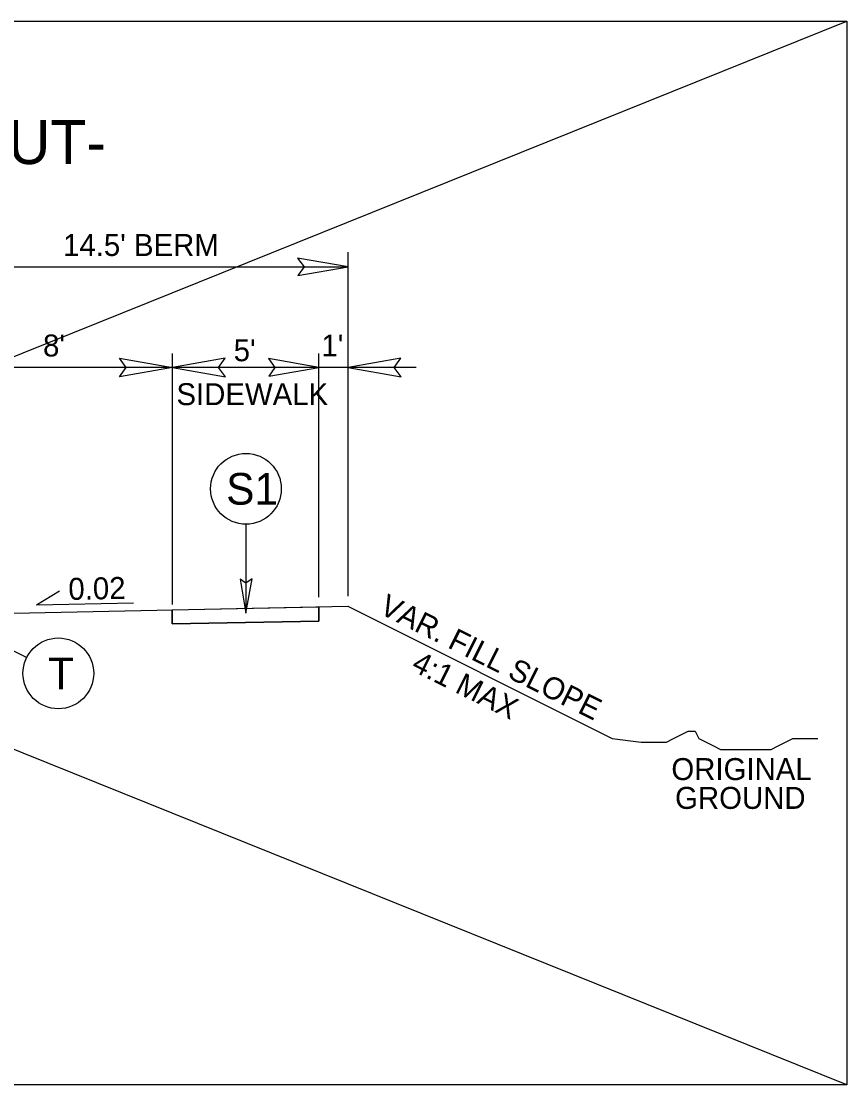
# Model space of a CAD drawing. Extents: x 1487909 to 1489267, y 497866 to 499814.
# Drawn here: x 1489239.04 to 1489267.23, y 498144.27 to 498180.57 of the extents above; entities that cross this region are included whole.
import ezdxf

# ---------------------------------------------------------------- set-up
doc = ezdxf.new("R2010")
doc.units = 0
for name, color, linetype in [('Prop Conc 4in Sidewalk', 7, 'Continuous'), ('Prop Dimension', 7, 'Continuous'), ('Prop Dimension Text', 7, 'Continuous'), ('Prop Shade Light', 7, 'Continuous'), ('Prop Terminator CELL', 7, 'Continuous'), ('Scratch_Level_3', 7, 'Continuous'), ('Typical Hinge Slope Arterial CELL', 7, 'Continuous'), ('Typical Hinge Slope Interstate CELL', 7, 'Continuous'), ('Typical ID Circle CELL', 7, 'Continuous'), ('Typical Pavement Slope CELL', 7, 'Continuous'), ('Typical Pavement Slope Information CELL', 7, 'Continuous'), ('Typical Terminator CELL', 7, 'Continuous'), ('Typical Text ID Circle CELL', 7, 'Continuous')]:
    doc.layers.add(name, color=color, linetype=linetype)

msp = doc.modelspace()

# ---------------------------------------------------------------- linework, layer by layer
at = {"layer": 'Prop Conc 4in Sidewalk'}
for p, q in [((1489244.198, 498160.48), (1489249.198, 498160.58)), ((1489249.198, 498160.099), (1489249.198, 498160.58)), ((1489244.198, 498160.48), (1489244.198, 498159.999)), ((1489244.198, 498159.999), (1489249.198, 498160.099))]:
    msp.add_line(p, q, dxfattribs=at)
at = {"layer": 'Prop Dimension'}
for p, q in [((1489250.199, 498160.943), (1489250.199, 498172.686)), ((1489235.699, 498172.186), (1489250.199, 498172.186)), ((1489244.199, 498160.664), (1489244.199, 498169.227)), ((1489249.199, 498160.912), (1489249.199, 498169.227)), ((1489244.199, 498168.756), (1489236.199, 498168.756)), ((1489249.199, 498168.756), (1489244.199, 498168.756)), ((1489250.199, 498168.756), (1489249.199, 498168.756)), ((1489252.529, 498168.756), (1489250.199, 498168.756))]:
    msp.add_line(p, q, dxfattribs=at)
at = {"layer": 'Prop Shade Light'}
for p, q in [((1489244.198, 498160.48), (1489249.198, 498160.58)), ((1489249.198, 498160.58), (1489249.198, 498160.099)), ((1489244.198, 498159.999), (1489244.198, 498160.48)), ((1489249.198, 498160.099), (1489244.198, 498159.999))]:
    msp.add_line(p, q, dxfattribs=at)
at = {"layer": 'Prop Terminator CELL'}
for points in [[(1489248.489, 498171.891), (1489250.199, 498172.186), (1489248.479, 498172.49), (1489248.698, 498172.186)], [(1489242.399, 498169.066), (1489244.199, 498168.756), (1489242.389, 498168.436), (1489242.619, 498168.756)], [(1489245.999, 498169.066), (1489244.199, 498168.756), (1489246.009, 498168.436), (1489245.779, 498168.756)], [(1489247.489, 498168.461), (1489249.199, 498168.756), (1489247.479, 498169.06), (1489247.698, 498168.756)], [(1489251.999, 498169.066), (1489250.199, 498168.756), (1489252.009, 498168.436), (1489251.779, 498168.756)]]:
    msp.add_lwpolyline(points, close=True, dxfattribs=at)
at = {"layer": 'Scratch_Level_3'}
for p, q in [((1489176.952, 498144.269), (1489267.234, 498180.571)), ((1489267.234, 498144.269), (1489176.952, 498180.571))]:
    msp.add_line(p, q, dxfattribs=at)
msp.add_lwpolyline([(1489176.952, 498180.571), (1489267.234, 498180.571), (1489267.234, 498144.269), (1489176.952, 498144.269)], close=True, dxfattribs=at)
at = {"layer": 'Typical Hinge Slope Arterial CELL'}
msp.add_line((1489250.198, 498160.6), (1489259.227, 498156.086), dxfattribs=at)
msp.add_lwpolyline([(1489259.227, 498156.086), (1489260.213, 498155.963), (1489260.459, 498155.963), (1489260.829, 498155.963), (1489261.076, 498155.963), (1489261.322, 498156.086), (1489261.568, 498156.209), (1489261.815, 498156.333), (1489262.061, 498156.333), (1489262.185, 498156.086), (1489262.431, 498155.963), (1489262.678, 498155.839), (1489262.924, 498155.717), (1489263.17, 498155.717), (1489263.417, 498155.717), (1489263.663, 498155.717), (1489263.909, 498155.717), (1489264.156, 498155.717), (1489264.402, 498155.717), (1489264.648, 498155.717), (1489264.895, 498155.839), (1489265.141, 498155.963), (1489265.388, 498156.086), (1489265.758, 498156.086), (1489266.004, 498156.086), (1489266.25, 498156.086)], dxfattribs=at)
at = {"layer": 'Typical ID Circle CELL'}
for p, q in [((1489246.713, 498163.404), (1489246.713, 498160.361)), ((1489239.223, 498158.85), (1489237.566, 498159.674))]:
    msp.add_line(p, q, dxfattribs=at)
for centre in [(1489246.713, 498164.612), (1489240.305, 498158.312)]:
    msp.add_circle(centre, 1.208, dxfattribs=at)
at = {"layer": 'Typical Pavement Slope CELL'}
msp.add_line((1489236.198, 498160.32), (1489250.198, 498160.6), dxfattribs=at)
at = {"layer": 'Typical Pavement Slope Information CELL'}
for q in [(1489240.341, 498161.13), (1489242.874, 498160.723)]:
    msp.add_line((1489239.558, 498160.656), q, dxfattribs=at)
at = {"layer": 'Typical Terminator CELL'}
msp.add_lwpolyline([(1489246.511, 498161.532), (1489246.713, 498160.361), (1489246.921, 498161.539), (1489246.713, 498161.389)], close=True, dxfattribs=at)
msp.add_lwpolyline([(1489246.511, 498161.532), (1489246.713, 498160.361), (1489246.921, 498161.539), (1489246.713, 498161.389)], close=True, dxfattribs=at)

# ---------------------------------------------------------------- texts
at = {"layer": 'Prop Dimension Text'}
for s, p in [("14.5' BERM", (1489240.466, 498172.559)), ("8'", (1489239.783, 498169.129)), ("5'", (1489246.294, 498168.967)), ("1'", (1489249.291, 498169.129)), ('SIDEWALK', (1489244.339, 498167.467))]:
    msp.add_text(s, height=0.75, dxfattribs=at).set_placement(p)
at = {"layer": 'Typical Hinge Slope Arterial CELL'}
for s, p in [('VAR. FILL SLOPE', (1489251.224, 498160.377)), ('4:1 MAX', (1489252.321, 498158.432))]:
    msp.add_text(s, height=0.75, rotation=333.4658, dxfattribs=at).set_placement(p)
for s, p in [('ORIGINAL', (1489261.244, 498154.669)), ('GROUND', (1489261.37, 498153.686))]:
    msp.add_text(s, height=0.75, dxfattribs=at).set_placement(p)
at = {"layer": 'Typical Hinge Slope Interstate CELL'}
msp.add_text('C -Y_DEV- & -Y_FUT-', height=1.5, dxfattribs=at).set_placement((1489221.868, 498175.697))
at = {"layer": 'Typical Pavement Slope Information CELL'}
msp.add_text('0.02', height=0.75, rotation=1.1457, dxfattribs=at).set_placement((1489240.655, 498160.817))
at = {"layer": 'Typical Text ID Circle CELL'}
for s, height, p in [('S1', 1.0817, (1489246.038, 498164.071)), ('T', 1.082, (1489239.95, 498157.771))]:
    msp.add_text(s, height=height, dxfattribs=at).set_placement(p)

doc.saveas('drawing.dxf')
